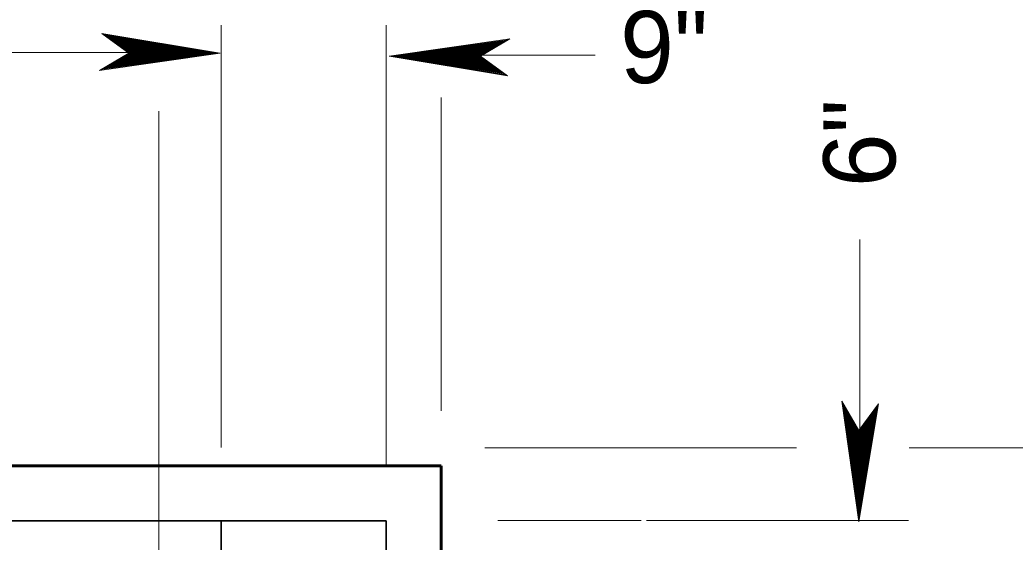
# Model space of a CAD drawing. Extents: x 144 to 252, y 360 to 425.
# Drawn here: x 178.382 to 182.906, y 400.112 to 402.487 of the extents above; entities that cross this region are included whole.
import ezdxf

# ---------------------------------------------------------------- set-up
doc = ezdxf.new("R2010")
doc.units = 0
doc.header["$LTSCALE"] = 0.13
for name, color, linetype, lineweight in [('1', 7, 'Continuous', 40), ('16', 7, 'Continuous', 13), ('3', 7, 'Continuous', 13)]:
    doc.layers.add(name, color=color, linetype=linetype, lineweight=lineweight)

msp = doc.modelspace()

# ---------------------------------------------------------------- linework, layer by layer
at = {"layer": '1', "lineweight": 13}
for p, q in [((179.148, 402.3377), (177.3103, 402.3377)), ((180.9972, 402.3256), (180.1221, 402.3256)), ((180.2978, 401.4728), (180.2978, 402.1089)), ((180.2978, 401.4728), (180.2978, 402.108)), ((180.2978, 400.7928), (180.2978, 401.7415)), ((182.2006, 400.3253), (182.2006, 401.4886)), ((180.2978, 401.0428), (180.2978, 401.3683)), ((180.2978, 400.7095), (180.2978, 400.8325)), ((182.2047, 400.2699), (182.2047, 400.5752)), ((181.9128, 400.5411), (180.4962, 400.5411)), ((184.4158, 400.5411), (182.4244, 400.5411)), ((181.2062, 400.2099), (180.5544, 400.2099)), ((182.4215, 400.2099), (181.2307, 400.2099))]:
    msp.add_line(p, q, dxfattribs=at)
at = {"layer": '1', "lineweight": 60}
for p, q in [((156.2978, 400.4595), (180.2978, 400.4595)), ((156.2978, 400.4595), (180.2978, 400.4595)), ((180.2978, 400.4595), (180.2978, 397.8819)), ((180.2978, 400.4595), (180.2978, 397.8819))]:
    msp.add_line(p, q, dxfattribs=at)
at = {"layer": '1', "lineweight": 35}
for p, q in [((168.3901, 400.2095), (180.0478, 400.2095)), ((179.2978, 397.8819), (179.2978, 400.2095))]:
    msp.add_line(p, q, dxfattribs=at)
msp.add_lwpolyline([(180.0478, 395.4595), (180.0478, 397.8819), (180.0478, 400.2095)], dxfattribs=at)
at = {"layer": '3'}
for p, q in [((179.2978, 401.8653), (179.2978, 402.4622)), ((180.0478, 401.4792), (180.0478, 402.4622)), ((179.2926, 402.3347), (178.7549, 402.424)), ((178.7549, 402.424), (178.8774, 402.3349)), ((179.2782, 402.3354), (178.7582, 402.4217)), ((179.2673, 402.3354), (178.7614, 402.4193)), ((179.2529, 402.3354), (178.7657, 402.4162)), ((179.2402, 402.3354), (178.7694, 402.4135)), ((179.2288, 402.3354), (178.7728, 402.4111)), ((179.2144, 402.3354), (178.777, 402.4079)), ((179.2017, 402.3354), (178.7807, 402.4052)), ((179.1879, 402.3354), (178.7848, 402.4022)), ((179.1741, 402.3354), (178.7889, 402.3992)), ((179.1608, 402.3354), (178.7928, 402.3964)), ((179.1469, 402.3354), (178.7969, 402.3934)), ((179.1343, 402.3354), (178.8007, 402.3907)), ((179.1229, 402.3354), (178.8041, 402.3882)), ((179.1072, 402.3354), (178.8087, 402.3849)), ((179.0934, 402.3354), (178.8127, 402.3819)), ((179.0754, 402.3359), (178.817, 402.3788)), ((179.0615, 402.3359), (178.8212, 402.3758)), ((179.0483, 402.3359), (178.825, 402.373)), ((179.0392, 402.3354), (178.8287, 402.3702)), ((180.6098, 402.3998), (180.0611, 402.3221)), ((180.6038, 402.3963), (180.0755, 402.3214)), ((180.6003, 402.3943), (180.0863, 402.3214)), ((180.5957, 402.3917), (180.1008, 402.3214)), ((180.5917, 402.3893), (180.1135, 402.3214)), ((180.5917, 402.3893), (180.1135, 402.3214)), ((180.588, 402.3871), (180.1248, 402.3214)), ((180.5834, 402.3844), (180.1393, 402.3214)), ((180.5793, 402.382), (180.152, 402.3214)), ((180.5749, 402.3795), (180.1658, 402.3214)), ((180.5705, 402.3769), (180.1796, 402.3214)), ((180.5662, 402.3744), (180.1928, 402.3214)), ((180.5617, 402.3717), (180.2067, 402.3214)), ((180.5577, 402.3695), (180.2193, 402.3214)), ((180.4762, 402.3219), (180.6098, 402.3998)), ((178.8774, 402.3349), (178.7438, 402.257)), ((178.7438, 402.257), (179.2926, 402.3347)), ((178.7498, 402.2605), (179.2782, 402.3354)), ((178.7533, 402.2625), (179.2673, 402.3354)), ((178.7579, 402.2652), (179.2529, 402.3354)), ((178.762, 402.2676), (179.2402, 402.3354)), ((178.762, 402.2676), (179.2402, 402.3354)), ((178.7657, 402.2697), (179.2288, 402.3354)), ((178.7703, 402.2724), (179.2144, 402.3354)), ((178.7743, 402.2748), (179.2017, 402.3354)), ((178.7788, 402.2773), (179.1879, 402.3354)), ((178.7832, 402.2799), (179.1741, 402.3354)), ((178.7874, 402.2824), (179.1608, 402.3354)), ((178.7919, 402.2851), (179.1469, 402.3354)), ((178.7959, 402.2873), (179.1343, 402.3354)), ((178.7997, 402.2896), (179.1229, 402.3354)), ((178.8047, 402.2924), (179.1072, 402.3354)), ((178.8091, 402.2951), (179.0934, 402.3354)), ((178.8131, 402.2973), (179.0738, 402.3343)), ((178.8162, 402.2992), (179.0754, 402.3359)), ((178.8207, 402.3018), (179.0615, 402.3359)), ((178.8249, 402.3043), (179.0483, 402.3359)), ((178.8264, 402.3052), (179.0392, 402.3354)), ((178.8303, 402.3074), (179.0272, 402.3354)), ((179.0272, 402.3354), (178.8323, 402.3677)), ((178.8347, 402.3101), (179.0134, 402.3354)), ((179.0134, 402.3354), (178.8364, 402.3647)), ((178.8397, 402.3129), (178.9977, 402.3354)), ((178.9977, 402.3354), (178.8411, 402.3614)), ((178.8438, 402.3153), (178.9852, 402.3354)), ((178.9852, 402.3354), (178.8448, 402.3587)), ((178.8481, 402.3178), (178.9719, 402.3354)), ((178.9719, 402.3354), (178.8487, 402.3558)), ((178.8519, 402.3201), (178.9599, 402.3354)), ((178.9599, 402.3354), (178.8522, 402.3532)), ((178.9454, 402.3354), (178.8565, 402.3502)), ((178.8566, 402.3227), (178.9454, 402.3354)), ((178.9316, 402.3354), (178.8607, 402.3472)), ((178.861, 402.3253), (178.9316, 402.3354)), ((178.9189, 402.3354), (178.8643, 402.3444)), ((178.8651, 402.3277), (178.9189, 402.3354)), ((178.9057, 402.3354), (178.8682, 402.3416)), ((178.8703, 402.3307), (178.8954, 402.3343)), ((178.8942, 402.3354), (178.8717, 402.3392)), ((178.873, 402.3323), (178.8942, 402.3354)), ((178.8841, 402.3354), (178.8747, 402.3369)), ((178.8772, 402.3347), (179.2926, 402.3347)), ((180.554, 402.3673), (180.2308, 402.3214)), ((180.549, 402.3644), (180.2464, 402.3214)), ((180.5446, 402.3617), (180.2602, 402.3214)), ((180.5374, 402.3576), (180.2782, 402.3209)), ((180.5406, 402.3595), (180.2798, 402.3225)), ((180.533, 402.355), (180.2922, 402.3209)), ((180.5288, 402.3525), (180.3053, 402.3209)), ((180.5272, 402.3517), (180.3144, 402.3214)), ((180.5233, 402.3494), (180.3264, 402.3214)), ((180.5189, 402.3467), (180.3402, 402.3214)), ((180.5139, 402.3439), (180.3559, 402.3214)), ((180.5098, 402.3415), (180.3685, 402.3214)), ((180.5056, 402.339), (180.3817, 402.3214)), ((180.5017, 402.3367), (180.3937, 402.3214)), ((180.4971, 402.3341), (180.4082, 402.3214)), ((180.4927, 402.3315), (180.4221, 402.3214)), ((180.4886, 402.3292), (180.4348, 402.3214)), ((180.4833, 402.3261), (180.4582, 402.3225)), ((180.4807, 402.3245), (180.4594, 402.3214)), ((180.0611, 402.3221), (180.5987, 402.2328)), ((180.4765, 402.3221), (180.0611, 402.3221)), ((180.0755, 402.3214), (180.5955, 402.2352)), ((180.0863, 402.3214), (180.5923, 402.2375)), ((180.1008, 402.3214), (180.588, 402.2407)), ((180.1135, 402.3214), (180.5842, 402.2433)), ((180.1248, 402.3214), (180.5809, 402.2457)), ((180.1393, 402.3214), (180.5767, 402.2489)), ((180.152, 402.3214), (180.5729, 402.2517)), ((180.1658, 402.3214), (180.5688, 402.2546)), ((180.1796, 402.3214), (180.5648, 402.2576)), ((180.1928, 402.3214), (180.5608, 402.2604)), ((180.2067, 402.3214), (180.5567, 402.2634)), ((180.2193, 402.3214), (180.553, 402.2661)), ((180.2308, 402.3214), (180.5496, 402.2686)), ((180.2464, 402.3214), (180.545, 402.2719)), ((180.2602, 402.3214), (180.5409, 402.2749)), ((180.2782, 402.3209), (180.5367, 402.278)), ((180.2922, 402.3209), (180.5325, 402.281)), ((180.3053, 402.3209), (180.5287, 402.2838)), ((180.3144, 402.3214), (180.5249, 402.2866)), ((180.3264, 402.3214), (180.5213, 402.2892)), ((180.3402, 402.3214), (180.5172, 402.2922)), ((180.3559, 402.3214), (180.5126, 402.2954)), ((180.3685, 402.3214), (180.5089, 402.2982)), ((180.3817, 402.3214), (180.505, 402.301)), ((180.3937, 402.3214), (180.5014, 402.3037)), ((180.4082, 402.3214), (180.4972, 402.3067)), ((180.4221, 402.3214), (180.493, 402.3097)), ((180.4348, 402.3214), (180.4893, 402.3124)), ((180.448, 402.3214), (180.4854, 402.3152)), ((180.4594, 402.3214), (180.482, 402.3177)), ((180.4696, 402.3214), (180.479, 402.3199)), ((180.5987, 402.2328), (180.4762, 402.3219)), ((179.2978, 401.4812), (179.2978, 402.2346)), ((180.2978, 401.4728), (180.2978, 402.1332)), ((179.0137, 401.8533), (179.0137, 402.0723)), ((179.0137, 399.4644), (179.0137, 401.9466)), ((179.2978, 400.5428), (179.2978, 401.8661)), ((180.0478, 400.4595), (180.0478, 401.5232)), ((180.2978, 400.7928), (180.2978, 401.3683)), ((180.2978, 400.7095), (180.2978, 400.8325)), ((179.0137, 399.4644), (179.0137, 400.8191)), ((179.2978, 400.6701), (179.2978, 400.8191)), ((180.0478, 400.6815), (180.0478, 400.8191)), ((182.1186, 400.7528), (182.1963, 400.2041)), ((182.1965, 400.6192), (182.1186, 400.7528)), ((182.1221, 400.7468), (182.197, 400.2185)), ((182.1241, 400.7433), (182.197, 400.2293)), ((182.1963, 400.2041), (182.2856, 400.7417)), ((182.2856, 400.7417), (182.1965, 400.6192)), ((182.1267, 400.7387), (182.197, 400.2437)), ((182.1292, 400.7347), (182.197, 400.2565)), ((182.1292, 400.7347), (182.197, 400.2565)), ((182.1313, 400.731), (182.197, 400.2678)), ((182.134, 400.7264), (182.197, 400.2822)), ((182.1364, 400.7223), (182.197, 400.295)), ((182.1389, 400.7179), (182.197, 400.3087)), ((182.1415, 400.7135), (182.197, 400.3226)), ((182.144, 400.7092), (182.197, 400.3358)), ((182.1467, 400.7047), (182.197, 400.3497)), ((182.1489, 400.7007), (182.197, 400.3623)), ((182.1512, 400.697), (182.197, 400.3737)), ((182.197, 400.2185), (182.2832, 400.7385)), ((182.197, 400.2293), (182.2809, 400.7353)), ((182.197, 400.2437), (182.2777, 400.731)), ((182.197, 400.2565), (182.2751, 400.7272)), ((182.197, 400.2678), (182.2727, 400.7239)), ((182.197, 400.2822), (182.2695, 400.7197)), ((182.197, 400.295), (182.2668, 400.7159)), ((182.197, 400.3087), (182.2638, 400.7118)), ((182.197, 400.3226), (182.2608, 400.7077)), ((182.197, 400.3358), (182.258, 400.7038)), ((182.197, 400.3497), (182.255, 400.6997)), ((182.197, 400.3623), (182.2523, 400.696)), ((182.154, 400.692), (182.197, 400.3894)), ((182.1567, 400.6876), (182.197, 400.4033)), ((182.1589, 400.6836), (182.1959, 400.4228)), ((182.1608, 400.6804), (182.1975, 400.4212)), ((182.1634, 400.676), (182.1975, 400.4352)), ((182.1659, 400.6717), (182.1975, 400.4483)), ((182.1668, 400.6703), (182.197, 400.4574)), ((182.169, 400.6663), (182.197, 400.4694)), ((182.1717, 400.6619), (182.197, 400.4832)), ((182.1745, 400.6569), (182.197, 400.4989)), ((182.1769, 400.6528), (182.197, 400.5115)), ((182.197, 400.3737), (182.2498, 400.6926)), ((182.197, 400.3894), (182.2465, 400.688)), ((182.197, 400.4033), (182.2435, 400.6839)), ((182.197, 400.4574), (182.2318, 400.6679)), ((182.197, 400.4694), (182.2293, 400.6643)), ((182.197, 400.4832), (182.2262, 400.6602)), ((182.197, 400.4989), (182.223, 400.6556)), ((182.197, 400.5115), (182.2202, 400.6519)), ((182.1975, 400.4212), (182.2404, 400.6797)), ((182.1975, 400.4352), (182.2374, 400.6755)), ((182.1975, 400.4483), (182.2346, 400.6717)), ((182.1794, 400.6486), (182.197, 400.5247)), ((182.1817, 400.6447), (182.197, 400.5367)), ((182.1843, 400.6401), (182.197, 400.5512)), ((182.1869, 400.6357), (182.197, 400.5651)), ((182.1892, 400.6316), (182.197, 400.5777)), ((182.1923, 400.6263), (182.1959, 400.6012)), ((182.1939, 400.6237), (182.197, 400.6024)), ((182.1963, 400.6195), (182.1963, 400.2041)), ((182.197, 400.5247), (182.2174, 400.648)), ((182.197, 400.5367), (182.2147, 400.6444)), ((182.197, 400.5512), (182.2117, 400.6402)), ((182.197, 400.5651), (182.2087, 400.636)), ((182.197, 400.5777), (182.206, 400.6323)), ((182.197, 400.591), (182.2032, 400.6284)), ((182.197, 400.6024), (182.2007, 400.625)), ((182.197, 400.6126), (182.1985, 400.622))]:
    msp.add_line(p, q, dxfattribs=at)

# ---------------------------------------------------------------- texts
at = {"layer": '16'}
msp.add_text('9"', height=0.3281, dxfattribs=at).set_placement((181.1109, 402.1992))
msp.add_text('6"', height=0.3281, rotation=90, dxfattribs=at).set_placement((182.3623, 401.7263))

doc.saveas('drawing.dxf')
